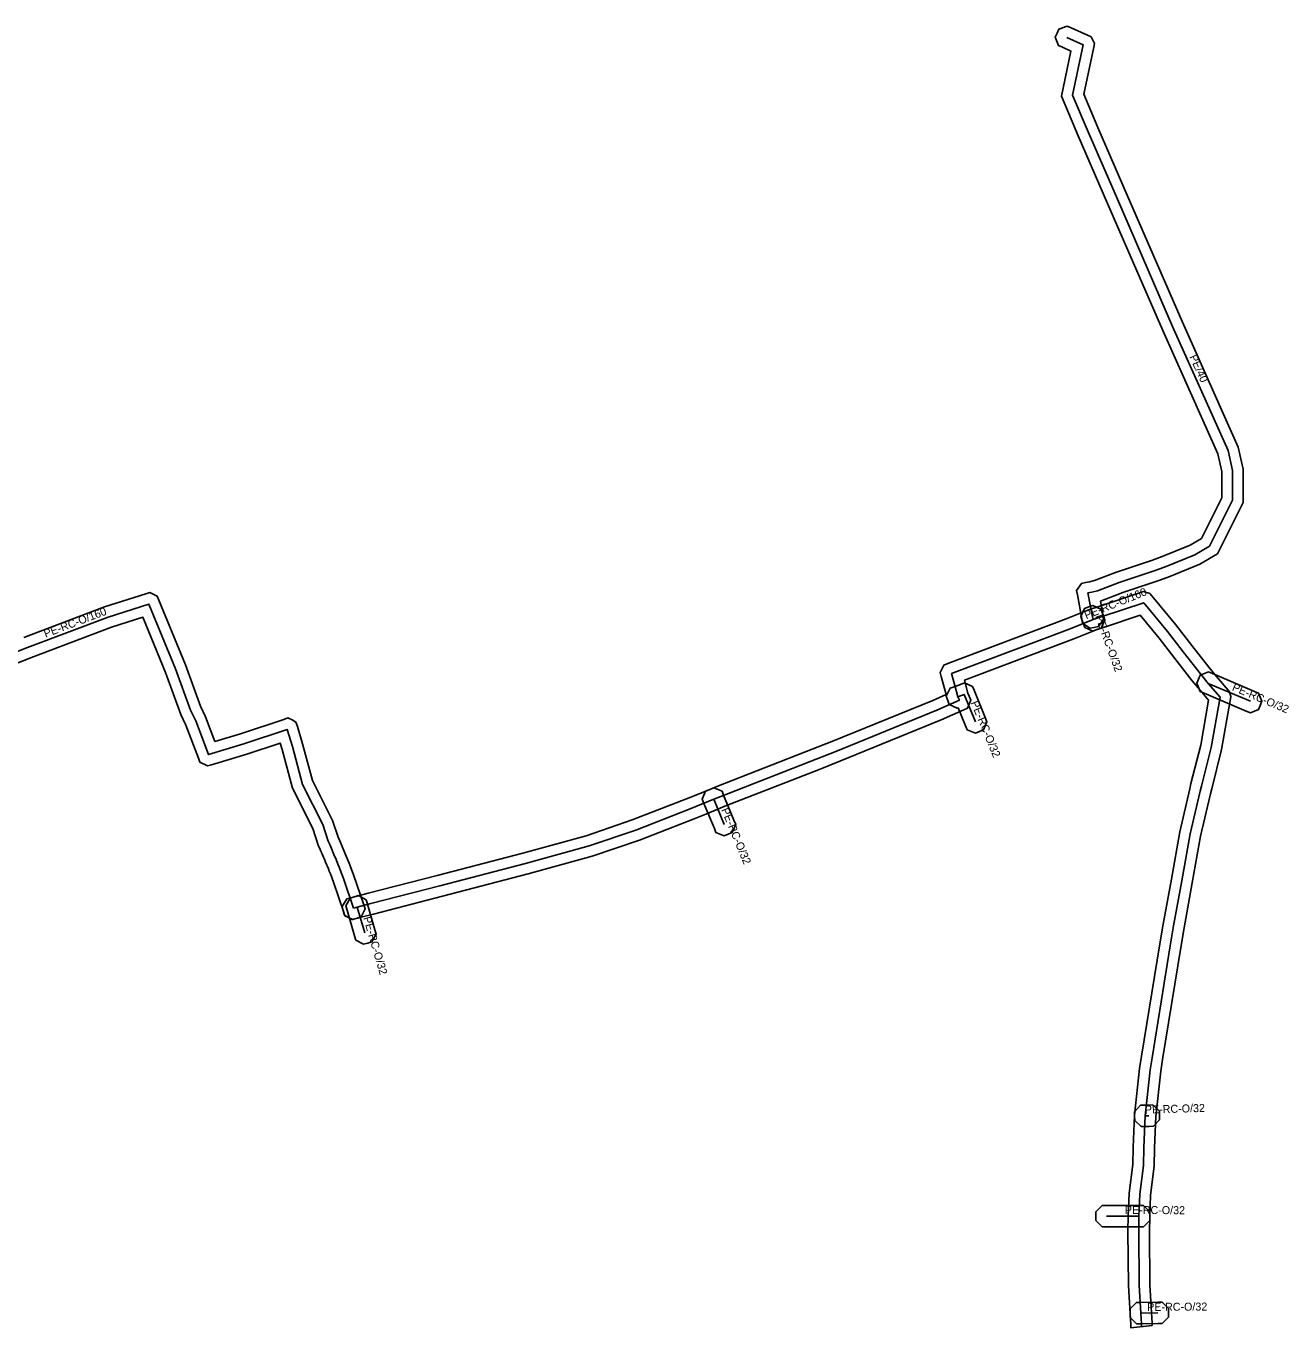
# Model space of a CAD drawing. Extents: x -783553 to -783321, y -1065190 to -1064961.
# Drawn here: x -783439.3 to -783321, y -1065174.8 to -1065052.8 of the extents above; entities that cross this region are included whole.
import ezdxf

# ---------------------------------------------------------------- set-up
doc = ezdxf.new("R2010")
doc.units = 0
for name, color, linetype in [('1', 7, 'Continuous'), ('30', 7, 'Continuous'), ('Plyn', 7, 'Continuous')]:
    doc.layers.add(name, color=color, linetype=linetype)

msp = doc.modelspace()

# ---------------------------------------------------------------- linework, layer by layer
at = {"layer": '1'}
for points in [[(-783338.64, -1065106.73), (-783338.66, -1065106.74), (-783338.43, -1065108.03), (-783338.35, -1065108.44), (-783338.82, -1065109.12), (-783339.23, -1065109.19), (-783339.64, -1065109.27), (-783340.32, -1065108.8), (-783340.39, -1065108.39), (-783340.8, -1065106.15), (-783340.88, -1065105.75), (-783340.43, -1065105.08), (-783340.04, -1065105), (-783339.67, -1065104.91), (-783339.22, -1065104.81), (-783337.24, -1065104.05), (-783333.76, -1065102.89), (-783332.87, -1065102.56), (-783330.24, -1065101.48), (-783329.2, -1065100.87), (-783327.27, -1065097.04), (-783327.29, -1065094.6), (-783327.66, -1065092.94), (-783332.81, -1065081.39), (-783337.98, -1065069.48), (-783340.73, -1065063.14), (-783342.3, -1065059.42), (-783341.41, -1065055.2), (-783342.21, -1065054.84), (-783342.59, -1065054.67), (-783342.88, -1065053.9), (-783342.71, -1065053.52), (-783342.54, -1065053.14), (-783341.77, -1065052.85), (-783341.39, -1065053.02), (-783339.85, -1065053.71), (-783339.53, -1065053.85), (-783339.21, -1065054.48), (-783339.28, -1065054.83), (-783340.22, -1065059.22), (-783338.89, -1065062.36), (-783336.14, -1065068.68), (-783330.97, -1065080.59), (-783325.74, -1065092.32), (-783325.29, -1065094.38), (-783325.27, -1065097.5), (-783327.68, -1065102.29), (-783329.35, -1065103.28), (-783332.15, -1065104.42), (-783333.1, -1065104.77), (-783336.56, -1065105.93)], [(-783333.8, -1065174.61), (-783335.79, -1065174.84), (-783335.8, -1065174.48), (-783335.86, -1065173.5), (-783336.01, -1065170.86), (-783336.07, -1065165.78), (-783336.04, -1065164.33), (-783335.97, -1065162.22), (-783335.62, -1065159.53), (-783335.58, -1065157.89), (-783335.45, -1065154.89), (-783334.98, -1065150.52), (-783334.81, -1065149.36), (-783333.1, -1065138.86), (-783332.79, -1065136.99), (-783332.01, -1065132.77), (-783331.23, -1065128.35), (-783330.29, -1065124.31), (-783330.17, -1065123.83), (-783329.26, -1065120.23), (-783328.52, -1065116.01), (-783329.31, -1065115.09), (-783330.07, -1065114.19), (-783331.68, -1065112.1), (-783333.14, -1065110.21), (-783334.93, -1065108.05), (-783338.27, -1065109.16), (-783338.97, -1065109.4), (-783341.13, -1065110.26), (-783351.39, -1065114.14), (-783351.33, -1065114.39), (-783351.06, -1065115.36), (-783350.95, -1065115.63), (-783350.79, -1065116.01), (-783351.09, -1065116.77), (-783351.46, -1065116.93), (-783353.58, -1065117.87), (-783363.06, -1065121.74), (-783364.92, -1065122.48), (-783373.84, -1065125.96), (-783374.49, -1065126.23), (-783375.63, -1065126.7), (-783376.7, -1065127.13), (-783381.84, -1065129.12), (-783386.25, -1065130.63), (-783392.25, -1065132.28), (-783400.3, -1065134.38), (-783406.75, -1065136.05), (-783408.02, -1065136.38), (-783408.36, -1065136.47), (-783408.77, -1065136.57), (-783409.48, -1065136.15), (-783409.58, -1065135.74), (-783409.68, -1065135.34), (-783409.26, -1065134.63), (-783408.86, -1065134.53), (-783408.52, -1065134.44), (-783407.25, -1065134.11), (-783400.8, -1065132.44), (-783392.77, -1065130.34), (-783386.83, -1065128.71), (-783382.52, -1065127.24), (-783377.44, -1065125.27), (-783376.39, -1065124.84), (-783375.25, -1065124.38), (-783374.58, -1065124.1), (-783365.66, -1065120.62), (-783363.8, -1065119.88), (-783354.36, -1065116.03), (-783353.1, -1065115.47), (-783353.26, -1065114.91), (-783353.56, -1065113.8), (-783353.67, -1065113.42), (-783353.32, -1065112.73), (-783352.95, -1065112.59), (-783341.85, -1065108.4), (-783339.67, -1065107.52), (-783338.91, -1065107.26), (-783334.91, -1065105.94), (-783334.62, -1065105.84), (-783334.03, -1065106.01), (-783333.83, -1065106.25), (-783331.58, -1065108.96), (-783330.1, -1065110.88), (-783328.51, -1065112.93), (-783327.79, -1065113.79), (-783326.69, -1065115.07), (-783326.55, -1065115.24), (-783326.43, -1065115.67), (-783326.46, -1065115.89), (-783327.3, -1065120.65), (-783328.23, -1065124.33), (-783328.35, -1065124.79), (-783329.27, -1065128.75), (-783330.05, -1065133.13), (-783330.82, -1065137.33), (-783331.12, -1065139.18), (-783332.83, -1065149.68), (-783333, -1065150.78), (-783333.45, -1065155.03), (-783333.58, -1065157.95), (-783333.62, -1065159.69), (-783333.97, -1065162.38), (-783334.04, -1065164.39), (-783334.07, -1065165.79), (-783334.01, -1065170.79), (-783333.86, -1065173.38), (-783333.8, -1065174.4)], [(-783340.12, -1065109.19), (-783340.26, -1065108.8), (-783340.35, -1065108.55), (-783340.49, -1065108.16), (-783340.14, -1065107.41), (-783339.75, -1065107.27), (-783339.36, -1065107.13), (-783338.61, -1065107.48), (-783338.47, -1065107.87), (-783338.38, -1065108.12), (-783338.24, -1065108.51), (-783338.59, -1065109.26), (-783338.98, -1065109.4), (-783339.37, -1065109.54)], [(-783328.54, -1065113.36), (-783328.16, -1065113.52), (-783324.21, -1065115.19), (-783323.83, -1065115.35), (-783323.52, -1065116.12), (-783323.68, -1065116.5), (-783323.84, -1065116.88), (-783324.61, -1065117.19), (-783324.99, -1065117.03), (-783328.94, -1065115.36), (-783329.32, -1065115.2), (-783329.63, -1065114.43), (-783329.47, -1065114.05), (-783329.31, -1065113.67)], [(-783351.29, -1065118.41), (-783351.97, -1065116.74), (-783352.06, -1065116.77), (-783352.81, -1065116.42), (-783352.95, -1065116.03), (-783353.09, -1065115.65), (-783352.74, -1065114.89), (-783352.35, -1065114.75), (-783351.75, -1065114.53), (-783351.38, -1065114.39), (-783350.64, -1065114.72), (-783350.48, -1065115.09), (-783349.44, -1065117.65), (-783349.28, -1065118.03), (-783349.6, -1065118.8), (-783349.98, -1065118.96), (-783350.36, -1065119.11), (-783351.13, -1065118.79)], [(-783374.1, -1065124.53), (-783373.95, -1065124.92), (-783372.98, -1065127.27), (-783372.82, -1065127.65), (-783373.14, -1065128.42), (-783373.52, -1065128.57), (-783373.9, -1065128.73), (-783374.67, -1065128.42), (-783374.82, -1065128.03), (-783375.79, -1065125.68), (-783375.95, -1065125.3), (-783375.64, -1065124.53), (-783375.25, -1065124.38), (-783374.87, -1065124.22)], [(-783407.43, -1065134.73), (-783407.31, -1065135.13), (-783406.61, -1065137.53), (-783406.49, -1065137.93), (-783406.89, -1065138.65), (-783407.29, -1065138.77), (-783407.69, -1065138.89), (-783408.41, -1065138.49), (-783408.53, -1065138.09), (-783409.23, -1065135.69), (-783409.35, -1065135.29), (-783408.95, -1065134.57), (-783408.55, -1065134.45), (-783408.15, -1065134.33)], [(-783334.89, -1065153.97), (-783334.48, -1065153.96), (-783334.15, -1065153.95), (-783333.74, -1065153.94), (-783333.13, -1065154.51), (-783333.12, -1065154.92), (-783333.11, -1065155.33), (-783333.68, -1065155.94), (-783334.09, -1065155.95), (-783334.42, -1065155.96), (-783334.83, -1065155.97), (-783335.44, -1065155.4), (-783335.45, -1065154.99), (-783335.46, -1065154.58)], [(-783338.5, -1065163.36), (-783338.09, -1065163.36), (-783336.96, -1065163.35), (-783335.04, -1065163.36), (-783334.62, -1065163.36), (-783334.04, -1065163.95), (-783334.04, -1065164.36), (-783334.04, -1065164.78), (-783334.63, -1065165.36), (-783335.05, -1065165.36), (-783336.96, -1065165.35), (-783338.07, -1065165.36), (-783338.48, -1065165.36), (-783339.08, -1065164.78), (-783339.08, -1065164.37), (-783339.08, -1065163.96)], [(-783332.86, -1065174.43), (-783333.27, -1065174.43), (-783334.85, -1065174.44), (-783335.27, -1065174.44), (-783335.86, -1065173.86), (-783335.86, -1065173.45), (-783335.86, -1065173.03), (-783335.28, -1065172.44), (-783334.87, -1065172.44), (-783333.29, -1065172.43), (-783332.87, -1065172.43), (-783332.28, -1065173.01), (-783332.28, -1065173.42), (-783332.28, -1065173.84)]]:
    msp.add_lwpolyline(points, close=True, dxfattribs=at)
msp.add_lwpolyline([(-783439.51, -1065110.15), (-783431.95, -1065107.28), (-783428.08, -1065106.06), (-783427.71, -1065105.94), (-783427, -1065106.27), (-783426.85, -1065106.63), (-783424.36, -1065112.71), (-783422.97, -1065116.57), (-783422.48, -1065117.56), (-783421.6, -1065119.88), (-783419.21, -1065119.17), (-783415.16, -1065117.81), (-783414.76, -1065117.68), (-783414.38, -1065117.87), (-783414.01, -1065118.06), (-783413.88, -1065118.47), (-783413.39, -1065120.09), (-783412.46, -1065123.54), (-783410.58, -1065127.28), (-783410.06, -1065128.86), (-783409.91, -1065129.18), (-783409.46, -1065130.25), (-783409.39, -1065130.42), (-783409.13, -1065131.06), (-783409.03, -1065131.28), (-783408.93, -1065131.55), (-783408.61, -1065132.39), (-783407.66, -1065135.18), (-783407.53, -1065135.57), (-783407.9, -1065136.31), (-783408.29, -1065136.44), (-783408.68, -1065136.58), (-783409.43, -1065136.21), (-783409.56, -1065135.82), (-783410.49, -1065133.07), (-783410.79, -1065132.27), (-783410.89, -1065132.03), (-783410.97, -1065131.82), (-783411.25, -1065131.18), (-783411.32, -1065130.99), (-783411.73, -1065130), (-783411.92, -1065129.6), (-783412.44, -1065128.04), (-783414.34, -1065124.26), (-783415.31, -1065120.65), (-783415.5, -1065120.03), (-783418.61, -1065121.07), (-783421.92, -1065122.07), (-783422.3, -1065122.18), (-783423.01, -1065121.83), (-783423.15, -1065121.46), (-783424.32, -1065118.36), (-783424.81, -1065117.35), (-783426.22, -1065113.43), (-783428.35, -1065108.24), (-783431.29, -1065109.18), (-783438.79, -1065112.01), (-783447.61, -1065115.48)], dxfattribs=at)
at = {"layer": 'Plyn'}
for points in [[(-783341.8, -1065053.93), (-783340.26, -1065054.62), (-783341.26, -1065059.32), (-783339.81, -1065062.75), (-783337.06, -1065069.08), (-783331.89, -1065080.99), (-783326.7, -1065092.63), (-783326.29, -1065094.49), (-783326.27, -1065097.27), (-783328.44, -1065101.58), (-783329.8, -1065102.38), (-783332.51, -1065103.49), (-783333.43, -1065103.83), (-783336.9, -1065104.99), (-783338.93, -1065105.77), (-783339.45, -1065105.89), (-783339.82, -1065105.97), (-783339.41, -1065108.21)], [(-783408.61, -1065135.5), (-783409.55, -1065132.73), (-783409.86, -1065131.91), (-783409.96, -1065131.66), (-783410.05, -1065131.44), (-783410.32, -1065130.8), (-783410.39, -1065130.62), (-783410.82, -1065129.59), (-783410.99, -1065129.23), (-783411.51, -1065127.66), (-783413.4, -1065123.9), (-783414.35, -1065120.37), (-783414.84, -1065118.76), (-783418.91, -1065120.12), (-783422.21, -1065121.11), (-783423.4, -1065117.96), (-783423.89, -1065116.96), (-783425.29, -1065113.07), (-783427.78, -1065107.01), (-783431.62, -1065108.23), (-783439.15, -1065111.08), (-783447.97, -1065114.55)], [(-783334.79, -1065174.72), (-783334.8, -1065174.44), (-783334.86, -1065173.44), (-783335.01, -1065170.83), (-783335.07, -1065165.79), (-783335.04, -1065164.36), (-783334.97, -1065162.3), (-783334.62, -1065159.61), (-783334.58, -1065157.92), (-783334.45, -1065154.96), (-783333.99, -1065150.65), (-783333.82, -1065149.52), (-783332.11, -1065139.02), (-783331.8, -1065137.16), (-783331.03, -1065132.95), (-783330.25, -1065128.55), (-783329.32, -1065124.55), (-783329.2, -1065124.08), (-783328.28, -1065120.44), (-783327.45, -1065115.72), (-783328.55, -1065114.44), (-783329.29, -1065113.56), (-783330.89, -1065111.49), (-783332.36, -1065109.58), (-783334.6, -1065106.89), (-783338.59, -1065108.21), (-783339.32, -1065108.46), (-783341.49, -1065109.33), (-783352.6, -1065113.53), (-783352.29, -1065114.65), (-783352.01, -1065115.69), (-783351.87, -1065116.02), (-783353.97, -1065116.95), (-783363.43, -1065120.81), (-783365.29, -1065121.55), (-783374.21, -1065125.03), (-783374.87, -1065125.3), (-783376.01, -1065125.77), (-783377.07, -1065126.2), (-783382.18, -1065128.18), (-783386.54, -1065129.67), (-783392.51, -1065131.31), (-783400.55, -1065133.41), (-783407, -1065135.08), (-783408.27, -1065135.41), (-783408.61, -1065135.5)], [(-783339.32, -1065108.46), (-783339.41, -1065108.21)], [(-783328.55, -1065114.44), (-783324.6, -1065116.11)], [(-783350.36, -1065118.03), (-783351.41, -1065115.47), (-783352.01, -1065115.69)], [(-783374.87, -1065125.3), (-783373.9, -1065127.65)], [(-783408.27, -1065135.41), (-783407.57, -1065137.81)], [(-783334.45, -1065154.96), (-783334.12, -1065154.95)], [(-783338.08, -1065164.36), (-783336.96, -1065164.35), (-783335.04, -1065164.36)], [(-783333.28, -1065173.43), (-783334.86, -1065173.44)]]:
    msp.add_lwpolyline(points, dxfattribs=at)

# ---------------------------------------------------------------- texts
at = {"layer": '30'}
for s, rotation, p in [('PE/40', 294.031, (-783330.33, -1065083.83)), ('PE-RC-O/160', 21.8469, (-783339.98, -1065108.44)), ('PE-RC-O/160', 20.731, (-783437.47, -1065110.17)), ('PE-RC-O/32', 289.7989, (-783339.17, -1065108.14)), ('PE-RC-O/32', 337.0821, (-783326.38, -1065115.07)), ('PE-RC-O/32', 292.3013, (-783350.81, -1065116.25)), ('PE-RC-O/32', 292.4292, (-783374.19, -1065126.28)), ('PE-RC-O/32', 286.2602, (-783407.72, -1065136.41)), ('PE-RC-O/32', 1.7357, (-783334.48, -1065154.76)), ('PE-RC-O/32', 359.7016, (-783336.36, -1065164.15)), ('PE-RC-O/32', 0.3626, (-783334.27, -1065173.24))]:
    msp.add_text(s, height=0.75, rotation=rotation, dxfattribs=at).set_placement(p)

doc.saveas('drawing.dxf')
